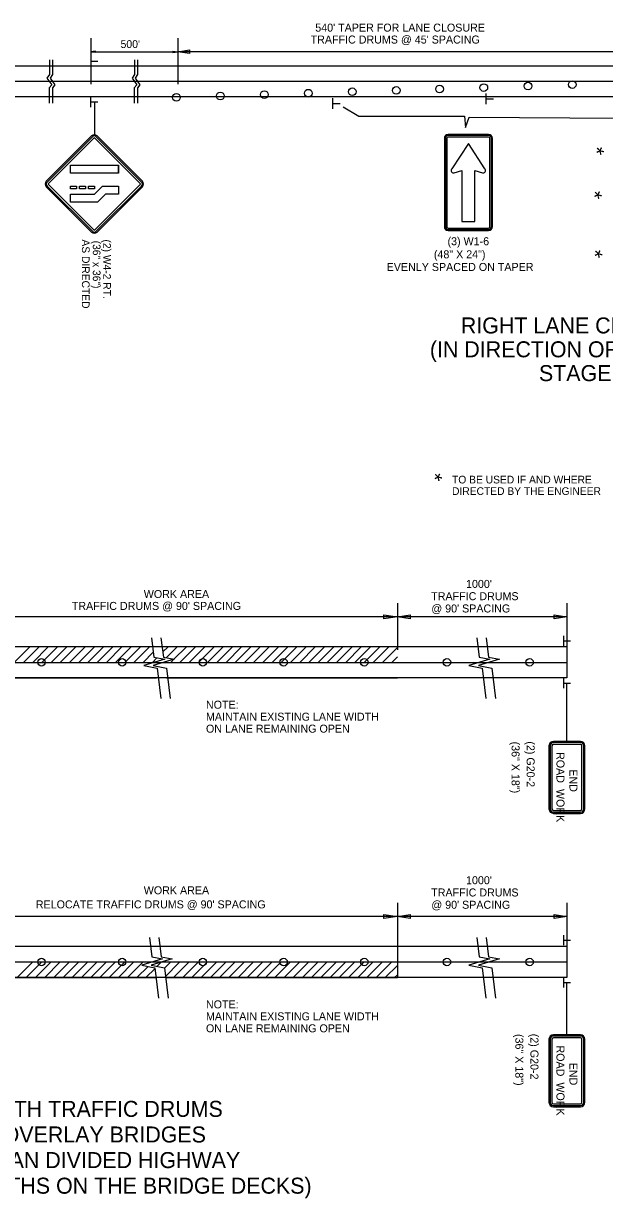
# Model space of a CAD drawing. Extents: x 1930579 to 1938222, y 596452 to 597559.
# Drawn here: x 1937236 to 1937672, y 596558 to 597439 of the extents above; entities that cross this region are included whole.
import ezdxf

# ---------------------------------------------------------------- set-up
doc = ezdxf.new("R2010")
doc.units = 0
for name, color, linetype in [('Default', 7, 'Continuous'), ('P_TC_Signs_Permanent', 7, 'Continuous'), ('P_TC_Signs_Temporary', 7, 'Continuous'), ('R_Border', 7, 'Continuous')]:
    doc.layers.add(name, color=color, linetype=linetype)

msp = doc.modelspace()

# ---------------------------------------------------------------- linework, layer by layer
at = {"layer": 'Default'}
for p, q in [((1937286.15, 597427.55), (1937286.15, 597393.08)), ((1937351.5, 597427.55), (1937351.5, 597393.08)), ((1937289.82, 597417.99), (1937286.15, 597417.44)), ((1937286.15, 597417.44), (1937351.5, 597417.44)), ((1937289.82, 597416.89), (1937286.15, 597417.44)), ((1937286.15, 597414.32), (1937286.15, 597406.66)), ((1937289.82, 597417.9), (1937286.76, 597417.44)), ((1937289.82, 597416.98), (1937286.76, 597417.44)), ((1937289.82, 597417.81), (1937287.4, 597417.44)), ((1937289.82, 597417.08), (1937287.4, 597417.44)), ((1937289.82, 597417.72), (1937288.01, 597417.44)), ((1937289.82, 597417.17), (1937288.01, 597417.44)), ((1937289.82, 597417.62), (1937288.63, 597417.44)), ((1937289.82, 597417.27), (1937288.63, 597417.44)), ((1937289.82, 597417.53), (1937289.24, 597417.44)), ((1937289.82, 597417.36), (1937289.24, 597417.44)), ((1937289.82, 597416.89), (1937289.82, 597417.99)), ((1937347.83, 597417.99), (1937351.5, 597417.44)), ((1937347.83, 597417.99), (1937347.83, 597416.89)), ((1937347.83, 597417.9), (1937350.89, 597417.44)), ((1937347.83, 597417.81), (1937350.25, 597417.44)), ((1937347.83, 597417.72), (1937349.64, 597417.44)), ((1937347.83, 597417.62), (1937349.02, 597417.44)), ((1937347.83, 597417.53), (1937348.41, 597417.44)), ((1937347.83, 597416.89), (1937351.5, 597417.44)), ((1937347.83, 597417.26), (1937349.02, 597417.44)), ((1937347.83, 597417.08), (1937350.25, 597417.44)), ((1937347.83, 597416.98), (1937350.89, 597417.44)), ((1937347.83, 597417.17), (1937349.64, 597417.44)), ((1937347.83, 597417.36), (1937348.41, 597417.44)), ((1937351.5, 597417.44), (1937360.36, 597418.77)), ((1937718.72, 597417.44), (1937351.5, 597417.44)), ((1937360.36, 597416.11), (1937351.5, 597417.44)), ((1937360.36, 597418.77), (1937360.36, 597416.11)), ((1937351.5, 597406.66), (1936683.76, 597406.66)), ((1937286.26, 597410.51), (1937291.49, 597410.51)), ((1937970.45, 597406.66), (1937351.5, 597406.66)), ((1937970.45, 597395.14), (1936683.76, 597395.14)), ((1937582.76, 597378.17), (1937582.76, 597386.15)), ((1937351.5, 597383.62), (1936683.76, 597383.62)), ((1937286.15, 597375.96), (1937286.15, 597383.62)), ((1937286.26, 597379.77), (1937291.49, 597379.77)), ((1937970.45, 597383.62), (1937351.5, 597383.62)), ((1937467.8, 597374.68), (1937467.8, 597382.66)), ((1937467.92, 597378.65), (1937473.37, 597378.65)), ((1937582.88, 597382.14), (1937588.33, 597382.14)), ((1937516.16, 597003.98), (1937516.16, 596968.94)), ((1937643.39, 597003.98), (1937643.39, 596947.87)), ((1937516.16, 596993.7), (1937188.67, 596993.7)), ((1937506.1, 596992.19), (1937506.1, 596995.2)), ((1937506.1, 596995.2), (1937516.16, 596993.7)), ((1937516.16, 596993.7), (1937506.1, 596992.19)), ((1937516.16, 596993.7), (1937525.82, 596995.15)), ((1937525.82, 596992.25), (1937516.16, 596993.7)), ((1937643.39, 596993.7), (1937516.16, 596993.7)), ((1937525.82, 596995.15), (1937525.82, 596992.25)), ((1937633.73, 596992.25), (1937633.73, 596995.15)), ((1937633.73, 596995.15), (1937643.39, 596993.7)), ((1937643.39, 596993.7), (1937633.73, 596992.25)), ((1937640.73, 596979.4), (1937640.73, 596971.92)), ((1937640.84, 596975.68), (1937645.95, 596975.68)), ((1937643.39, 596971.31), (1936696.54, 596971.31)), ((1937228.83, 596959.59), (1937240.55, 596971.31)), ((1937235.73, 596959.59), (1937247.45, 596971.31)), ((1937242.64, 596959.59), (1937254.36, 596971.31)), ((1937249.54, 596959.59), (1937261.26, 596971.31)), ((1937256.45, 596959.59), (1937268.17, 596971.31)), ((1937263.35, 596959.59), (1937275.07, 596971.31)), ((1937270.26, 596959.59), (1937281.98, 596971.31)), ((1937277.16, 596959.59), (1937288.88, 596971.31)), ((1937284.07, 596959.59), (1937295.79, 596971.31)), ((1937290.97, 596959.59), (1937302.69, 596971.31)), ((1937297.88, 596959.59), (1937309.6, 596971.31)), ((1937304.79, 596959.59), (1937316.5, 596971.31)), ((1937311.69, 596959.59), (1937323.41, 596971.31)), ((1937318.6, 596959.59), (1937330.31, 596971.31)), ((1937325.5, 596959.59), (1937333.09, 596967.18)), ((1937332.41, 596959.59), (1937335.81, 596962.99)), ((1937340.18, 596967.37), (1937344.13, 596971.31)), ((1937342.74, 596963.02), (1937351.03, 596971.31)), ((1937348.61, 596961.98), (1937357.94, 596971.31)), ((1937353.12, 596959.59), (1937364.84, 596971.31)), ((1937360.03, 596959.59), (1937371.75, 596971.31)), ((1937366.93, 596959.59), (1937378.65, 596971.31)), ((1937373.84, 596959.59), (1937385.56, 596971.31)), ((1937380.74, 596959.59), (1937392.46, 596971.31)), ((1937387.65, 596959.59), (1937399.37, 596971.31)), ((1937394.55, 596959.59), (1937406.27, 596971.31)), ((1937401.46, 596959.59), (1937413.18, 596971.31)), ((1937408.37, 596959.59), (1937420.08, 596971.31)), ((1937415.27, 596959.59), (1937426.99, 596971.31)), ((1937422.18, 596959.59), (1937433.89, 596971.31)), ((1937429.08, 596959.59), (1937440.8, 596971.31)), ((1937435.99, 596959.59), (1937447.71, 596971.31)), ((1937442.89, 596959.59), (1937454.61, 596971.31)), ((1937449.8, 596959.59), (1937461.52, 596971.31)), ((1937456.7, 596959.59), (1937468.42, 596971.31)), ((1937463.61, 596959.59), (1937475.33, 596971.31)), ((1937470.51, 596959.59), (1937482.23, 596971.31)), ((1937477.42, 596959.59), (1937489.14, 596971.31)), ((1937484.32, 596959.59), (1937496.04, 596971.31)), ((1937491.23, 596959.59), (1937502.95, 596971.31)), ((1937498.13, 596959.59), (1937509.85, 596971.31)), ((1937505.04, 596959.59), (1937516.16, 596970.71)), ((1937511.95, 596959.59), (1937516.16, 596963.8)), ((1936696.54, 596959.59), (1937643.39, 596959.59)), ((1937346.22, 596959.59), (1937348.52, 596961.89)), ((1937643.39, 596947.87), (1936696.54, 596947.87)), ((1937188.46, 596947.87), (1937335.53, 596947.87)), ((1937343, 596947.87), (1937516.16, 596947.87)), ((1937640.73, 596947.64), (1937640.73, 596940.16)), ((1937640.84, 596943.92), (1937645.95, 596943.92)), ((1937516.16, 596779.28), (1937516.16, 596723.17)), ((1937516.16, 596779.28), (1937516.16, 596744.24)), ((1937643.39, 596779.28), (1937643.39, 596723.17)), ((1937516.16, 596769), (1937188.67, 596769)), ((1937506.1, 596767.49), (1937506.1, 596770.5)), ((1937506.1, 596770.5), (1937516.16, 596769)), ((1937516.16, 596769), (1937506.1, 596767.49)), ((1937516.16, 596769), (1937525.82, 596770.45)), ((1937525.82, 596767.55), (1937516.16, 596769)), ((1937643.39, 596769), (1937516.16, 596769)), ((1937525.82, 596770.45), (1937525.82, 596767.55)), ((1937633.73, 596767.55), (1937633.73, 596770.45)), ((1937633.73, 596770.45), (1937643.39, 596769)), ((1937643.39, 596769), (1937633.73, 596767.55)), ((1937640.73, 596754.94), (1937640.73, 596747.46)), ((1937640.84, 596751.22), (1937645.95, 596751.22)), ((1937643.39, 596746.61), (1936696.54, 596746.61)), ((1936696.54, 596734.89), (1937643.39, 596734.89)), ((1937230.92, 596723.17), (1937242.64, 596734.89)), ((1937237.82, 596723.17), (1937249.54, 596734.89)), ((1937244.73, 596723.17), (1937256.45, 596734.89)), ((1937251.63, 596723.17), (1937263.35, 596734.89)), ((1937258.54, 596723.17), (1937270.26, 596734.89)), ((1937265.45, 596723.17), (1937277.16, 596734.89)), ((1937272.35, 596723.17), (1937284.07, 596734.89)), ((1937279.26, 596723.17), (1937290.97, 596734.89)), ((1937286.16, 596723.17), (1937297.88, 596734.89)), ((1937293.07, 596723.17), (1937304.79, 596734.89)), ((1937299.97, 596723.17), (1937311.69, 596734.89)), ((1937306.88, 596723.17), (1937318.6, 596734.89)), ((1937313.78, 596723.17), (1937325.5, 596734.89)), ((1937336.07, 596731.64), (1937339.31, 596734.89)), ((1937341.4, 596723.17), (1937353.12, 596734.89)), ((1937341.5, 596730.17), (1937346.22, 596734.89)), ((1937348.31, 596723.17), (1937360.03, 596734.89)), ((1937355.21, 596723.17), (1937366.93, 596734.89)), ((1937362.12, 596723.17), (1937373.84, 596734.89)), ((1937369.03, 596723.17), (1937380.74, 596734.89)), ((1937375.93, 596723.17), (1937387.65, 596734.89)), ((1937382.84, 596723.17), (1937394.55, 596734.89)), ((1937389.74, 596723.17), (1937401.46, 596734.89)), ((1937396.65, 596723.17), (1937408.37, 596734.89)), ((1937403.55, 596723.17), (1937415.27, 596734.89)), ((1937410.46, 596723.17), (1937422.18, 596734.89)), ((1937417.36, 596723.17), (1937429.08, 596734.89)), ((1937424.27, 596723.17), (1937435.99, 596734.89)), ((1937431.17, 596723.17), (1937442.89, 596734.89)), ((1937438.08, 596723.17), (1937449.8, 596734.89)), ((1937444.98, 596723.17), (1937456.7, 596734.89)), ((1937451.89, 596723.17), (1937463.61, 596734.89)), ((1937458.79, 596723.17), (1937470.51, 596734.89)), ((1937465.7, 596723.17), (1937477.42, 596734.89)), ((1937472.61, 596723.17), (1937484.32, 596734.89)), ((1937479.51, 596723.17), (1937491.23, 596734.89)), ((1937486.42, 596723.17), (1937498.13, 596734.89)), ((1937493.32, 596723.17), (1937505.04, 596734.89)), ((1937500.23, 596723.17), (1937511.95, 596734.89)), ((1937320.69, 596723.17), (1937329.13, 596731.61)), ((1937327.59, 596723.17), (1937334.41, 596729.99)), ((1937507.13, 596723.17), (1937516.16, 596732.19)), ((1937514.04, 596723.17), (1937516.16, 596725.29)), ((1937643.39, 596723.17), (1936696.54, 596723.17)), ((1937188.46, 596723.17), (1937335.53, 596723.17)), ((1937334.5, 596723.17), (1937335.15, 596723.82)), ((1937343, 596723.17), (1937516.16, 596723.17)), ((1937640.73, 596723.18), (1937640.73, 596715.7)), ((1937640.84, 596719.46), (1937645.95, 596719.46))]:
    msp.add_line(p, q, dxfattribs=at)
for points in [[(1937255.22, 597411.46), (1937255.22, 597400.51), (1937253.34, 597397.73), (1937256.99, 597392.74), (1937255.07, 597390.44), (1937255.07, 597378.82)], [(1937257.52, 597411.46), (1937257.52, 597400.41), (1937255.65, 597397.63), (1937259.29, 597392.65), (1937257.37, 597390.34), (1937257.37, 597378.82)], [(1937319.01, 597411.46), (1937319.01, 597400.51), (1937317.14, 597397.73), (1937320.79, 597392.74), (1937318.87, 597390.44), (1937318.87, 597378.82)], [(1937321.31, 597411.46), (1937321.31, 597400.41), (1937319.44, 597397.63), (1937323.09, 597392.65), (1937321.17, 597390.34), (1937321.17, 597378.82)], [(1937331.74, 596978.04), (1937333.57, 596963.38), (1937341.63, 596961.96), (1937325.98, 596957.22), (1937335.94, 596955.32), (1937338.69, 596932.48)], [(1937338.85, 596978.04), (1937340.68, 596963.38), (1937348.74, 596961.96), (1937333.09, 596957.22), (1937343.05, 596955.32), (1937345.8, 596932.48)], [(1937575.66, 596978.04), (1937577.49, 596963.38), (1937585.55, 596961.96), (1937569.9, 596957.22), (1937579.86, 596955.32), (1937582.61, 596932.48)], [(1937582.77, 596978.04), (1937584.6, 596963.38), (1937592.66, 596961.96), (1937577.01, 596957.22), (1937586.97, 596955.32), (1937589.72, 596932.48)], [(1937330.13, 596753.34), (1937331.97, 596738.68), (1937340.03, 596737.26), (1937324.38, 596732.52), (1937334.34, 596730.62), (1937337.08, 596707.78)], [(1937337.25, 596753.34), (1937339.08, 596738.68), (1937347.14, 596737.26), (1937331.49, 596732.52), (1937341.45, 596730.62), (1937344.2, 596707.78)], [(1937575.66, 596753.34), (1937577.49, 596738.68), (1937585.55, 596737.26), (1937569.9, 596732.52), (1937579.86, 596730.62), (1937582.61, 596707.78)], [(1937582.77, 596753.34), (1937584.6, 596738.68), (1937592.66, 596737.26), (1937577.01, 596732.52), (1937586.97, 596730.62), (1937589.72, 596707.78)]]:
    msp.add_lwpolyline(points, dxfattribs=at)
for centre, radius in [((1937614.18, 597391.71), 2.87), ((1937647.33, 597392.81), 2.87), ((1937350.42, 597383.25), 2.87), ((1937383.41, 597384.29), 2.87), ((1937416.39, 597385.33), 2.87), ((1937449.37, 597386.38), 2.87), ((1937482.36, 597387.42), 2.87), ((1937515.34, 597388.47), 2.87), ((1937547.87, 597389.51), 2.87), ((1937581.02, 597390.61), 2.87), ((1937249.21, 596959.59), 2.8), ((1937309.75, 596959.59), 2.8), ((1937370.29, 596959.59), 2.8), ((1937430.82, 596959.59), 2.8), ((1937491.36, 596959.59), 2.8), ((1937553.36, 596959.59), 2.8), ((1937615.36, 596959.59), 2.8), ((1937249.21, 596734.89), 2.8), ((1937309.75, 596734.89), 2.8), ((1937370.29, 596734.89), 2.8), ((1937430.82, 596734.89), 2.8), ((1937491.36, 596734.89), 2.8), ((1937553.36, 596734.89), 2.8), ((1937615.36, 596734.89), 2.8)]:
    msp.add_circle(centre, radius, dxfattribs=at)
at = {"layer": 'P_TC_Signs_Permanent'}
for p, q in [((1937252.82, 597320.38), (1937286.76, 597354.33)), ((1937551.41, 597352.55), (1937551.41, 597286.17)), ((1937552.16, 597352.55), (1937552.16, 597286.17)), ((1937553.29, 597352.55), (1937553.29, 597286.17)), ((1937584.6, 597355.36), (1937554.22, 597355.36)), ((1937584.6, 597354.61), (1937554.22, 597354.61)), ((1937584.6, 597353.49), (1937554.22, 597353.49)), ((1937585.54, 597286.17), (1937585.54, 597352.55)), ((1937586.66, 597286.17), (1937586.66, 597352.55)), ((1937587.41, 597286.17), (1937587.41, 597352.55)), ((1937306.88, 597326.3), (1937306.88, 597332.3)), ((1937286.76, 597282.2), (1937252.82, 597316.14)), ((1937324.94, 597316.14), (1937291, 597282.2)), ((1937554.22, 597285.24), (1937584.6, 597285.24)), ((1937554.22, 597284.11), (1937584.6, 597284.11)), ((1937554.22, 597283.36), (1937584.6, 597283.36))]:
    msp.add_line(p, q, dxfattribs=at)
for points in [[(1937287.39, 597353.69), (1937253.45, 597319.75)], [(1937254.51, 597318.69), (1937288.45, 597352.63)], [(1937289.3, 597352.63), (1937323.24, 597318.69)], [(1937324.3, 597319.75), (1937290.36, 597353.69)], [(1937291, 597354.33), (1937307.97, 597337.36), (1937324.94, 597320.38)], [(1937581.85, 597329.62), (1937569.41, 597348.61), (1937557, 597329.61)], [(1937558.78, 597326.66), (1937564.54, 597328.38), (1937564.54, 597290.11), (1937574.29, 597290.11), (1937574.29, 597328.38), (1937580.03, 597326.63)], [(1937253.45, 597316.78), (1937287.39, 597282.84)], [(1937288.45, 597283.9), (1937254.51, 597317.84)], [(1937323.24, 597317.84), (1937289.3, 597283.9)], [(1937290.36, 597282.84), (1937324.3, 597316.78)]]:
    msp.add_lwpolyline(points, dxfattribs=at)
for points in [[(1937270.88, 597326.3), (1937270.88, 597332.3), (1937306.88, 597332.3), (1937306.88, 597326.3)], [(1937270.88, 597314.66), (1937270.88, 597316.76), (1937275.38, 597316.76), (1937275.38, 597314.66)], [(1937270.88, 597304.76), (1937270.88, 597310.76), (1937288.88, 597310.76), (1937294.88, 597316.76), (1937306.88, 597316.76), (1937306.88, 597310.76), (1937297.36, 597310.76), (1937291.36, 597304.76)], [(1937277.63, 597314.66), (1937277.63, 597316.76), (1937282.13, 597316.76), (1937282.13, 597314.66)], [(1937284.38, 597314.66), (1937284.38, 597316.76), (1937288.88, 597316.76), (1937288.88, 597314.66)]]:
    msp.add_lwpolyline(points, close=True, dxfattribs=at)
for centre, radius, start, end in [((1937288.88, 597352.2), 3, 45, 135), ((1937288.88, 597352.2), 2.1, 45, 135), ((1937288.88, 597352.2), 0.6, 45, 135), ((1937554.22, 597352.55), 2.81, 90, 180), ((1937554.22, 597352.55), 2.06, 90, 180), ((1937554.22, 597352.55), 0.938, 90, 180), ((1937584.6, 597352.55), 2.81, 360, 90), ((1937584.6, 597352.55), 2.06, 360, 90), ((1937584.6, 597352.55), 0.938, 360, 90), ((1937558.29, 597328.36), 1.76, 146.59943, 285.96908), ((1937494.2, 597370.61), 75, 326.59943, 326.85697), ((1937580.53, 597328.36), 1.8, 254.03093, 33.47548), ((1937644.59, 597370.72), 75, 213.2286, 213.47548), ((1937254.94, 597318.26), 3, 135, 225), ((1937254.94, 597318.26), 2.1, 135, 225), ((1937254.94, 597318.26), 0.6, 135, 225), ((1937322.82, 597318.26), 0.6, 315, 45), ((1937322.82, 597318.26), 2.1, 315, 45), ((1937322.82, 597318.26), 3, 315, 45), ((1937288.88, 597284.32), 3, 225, 315), ((1937288.88, 597284.32), 2.1, 225, 315), ((1937288.88, 597284.32), 0.6, 225, 315), ((1937554.22, 597286.17), 2.81, 180, 270), ((1937554.22, 597286.17), 2.06, 180, 270), ((1937554.22, 597286.17), 0.937, 180, 270), ((1937584.6, 597286.17), 2.81, 270, 360), ((1937584.6, 597286.17), 2.06, 270, 360), ((1937584.6, 597286.17), 0.938, 270, 360)]:
    msp.add_arc(centre, radius, start, end, dxfattribs=at)
at = {"layer": 'P_TC_Signs_Temporary'}
for p, q in [((1937629.89, 596896.98), (1937629.89, 596849.73)), ((1937630.83, 596896.98), (1937630.83, 596849.73)), ((1937632.14, 596896.98), (1937632.14, 596849.73)), ((1937653.52, 596900.35), (1937633.27, 596900.35)), ((1937653.52, 596899.42), (1937633.27, 596899.42)), ((1937653.52, 596898.1), (1937633.27, 596898.1)), ((1937654.64, 596849.73), (1937654.64, 596896.98)), ((1937655.96, 596849.73), (1937655.96, 596896.98)), ((1937656.89, 596849.73), (1937656.89, 596896.98)), ((1937633.27, 596848.6), (1937653.52, 596848.6)), ((1937633.27, 596847.29), (1937653.52, 596847.29)), ((1937633.27, 596846.35), (1937653.52, 596846.35)), ((1937629.89, 596676.95), (1937629.89, 596629.7)), ((1937630.83, 596676.95), (1937630.83, 596629.7)), ((1937632.14, 596676.95), (1937632.14, 596629.7)), ((1937653.52, 596680.33), (1937633.27, 596680.33)), ((1937653.52, 596679.39), (1937633.27, 596679.39)), ((1937653.52, 596678.08), (1937633.27, 596678.08)), ((1937654.64, 596629.7), (1937654.64, 596676.95)), ((1937655.96, 596629.7), (1937655.96, 596676.95)), ((1937656.89, 596629.7), (1937656.89, 596676.95)), ((1937633.27, 596628.58), (1937653.52, 596628.58)), ((1937633.27, 596627.26), (1937653.52, 596627.26)), ((1937633.27, 596626.33), (1937653.52, 596626.33))]:
    msp.add_line(p, q, dxfattribs=at)
for centre, radius, start, end in [((1937633.27, 596896.98), 3.37, 90, 180), ((1937633.27, 596896.98), 2.44, 90, 180), ((1937633.27, 596896.98), 1.13, 90, 180), ((1937653.52, 596896.98), 3.37, 360, 90), ((1937653.52, 596896.98), 2.44, 360, 90), ((1937653.52, 596896.98), 1.13, 360, 90), ((1937633.27, 596849.73), 3.37, 180, 270), ((1937633.27, 596849.73), 2.44, 180, 270), ((1937633.27, 596849.73), 1.13, 180, 270), ((1937653.52, 596849.73), 2.44, 270, 360), ((1937653.52, 596849.73), 1.13, 270, 360), ((1937653.52, 596849.73), 3.38, 270, 360), ((1937633.27, 596676.95), 3.37, 90, 180), ((1937633.27, 596676.95), 2.44, 90, 180), ((1937633.27, 596676.95), 1.13, 90, 180), ((1937653.52, 596676.95), 3.37, 360, 90), ((1937653.52, 596676.95), 2.44, 360, 90), ((1937653.52, 596676.95), 1.13, 360, 90), ((1937633.27, 596629.7), 3.37, 180, 270), ((1937633.27, 596629.7), 2.44, 180, 270), ((1937633.27, 596629.7), 1.13, 180, 270), ((1937653.52, 596629.7), 2.44, 270, 360), ((1937653.52, 596629.7), 1.13, 270, 360), ((1937653.52, 596629.7), 3.38, 270, 360)]:
    msp.add_arc(centre, radius, start, end, dxfattribs=at)
at = {"layer": 'R_Border'}
for p, q in [((1937288.88, 597379.77), (1937288.88, 597355.2)), ((1937643.39, 596900.35), (1937643.39, 596943.92)), ((1937643.39, 596680.33), (1937643.39, 596719.46))]:
    msp.add_line(p, q, dxfattribs=at)
msp.add_lwpolyline([(1937475.48, 597376.04), (1937487.29, 597369.09), (1937566.49, 597369.09), (1937567.19, 597360.75), (1937569.97, 597368.39), (1937683.22, 597367.7), (1937696.42, 597379.52)], dxfattribs=at)

# ---------------------------------------------------------------- texts
at = {"layer": 'Default'}
for s, height, p in [("540' TAPER FOR LANE CLOSURE", 6, (1937454.6, 597432.54)), ("TRAFFIC DRUMS @ 45' SPACING ", 6, (1937451.11, 597423.59)), ("500'", 5.875, (1937308.51, 597420.24)), ('RIGHT LANE CLOSURE ', 12, (1937563.79, 597206.21)), ('(IN DIRECTION OF TRAFFIC)', 12, (1937540.55, 597188.33)), ('STAGE 2', 12, (1937622.37, 597170.46)), ("1000'", 6, (1937567.68, 597015.4)), ('WORK AREA', 6, (1937325.96, 597007.82)), ('TRAFFIC DRUMS ', 6, (1937541.56, 597006.2)), ("TRAFFIC DRUMS @ 90' SPACING", 6, (1937271.98, 596998.9)), ("@ 90' SPACING", 6, (1937541.66, 596996.99)), ("1000'", 6, (1937567.68, 596793.22)), ('WORK AREA', 6, (1937325.95, 596785.65)), ('TRAFFIC DRUMS ', 6, (1937541.56, 596784.03)), ("RELOCATE TRAFFIC DRUMS @ 90' SPACING", 6, (1937244.98, 596775.09)), ("@ 90' SPACING", 6, (1937541.66, 596774.81)), ('LANE CLOSURE WITH TRAFFIC DRUMS', 12, (1937080.32, 596618.76)), ('FOR POLYMER OVERLAY BRIDGES', 12, (1937098.84, 596599.56)), ('4 LANE GRASS MEDIAN DIVIDED HIGHWAY', 12, (1937064.83, 596580.36)), ('(VAR. CLEAR ROADWAY WIDTHS ON THE BRIDGE DECKS)', 12, (1936999.82, 596561.16))]:
    msp.add_text(s, height=height, rotation=360, dxfattribs=at).set_placement(p)
at = {"layer": 'P_TC_Signs_Temporary'}
for s, p in [('ROAD  WORK', (1937635.52, 596892.31)), ('END', (1937645.27, 596879.38)), ('ROAD  WORK', (1937635.52, 596672.29)), ('END', (1937645.27, 596659.36))]:
    msp.add_text(s, height=6, rotation=270, dxfattribs=at).set_placement(p)
at = {"layer": 'R_Border'}
for s, height, rotation, p in [('*', 11.52, 45, (1937672.03, 597335.03)), ('*', 11.52, 45, (1937670.45, 597301.99)), ('AS DIRECTED ', 5.76, 270, (1937279.57, 597276.69)), ('(36" x 36")', 5.76, 270, (1937287.73, 597275.81)), ('(2) W4-2 RT.', 5.76, 270, (1937295.53, 597276.69)), ('(3) W1-6', 6, 0.00754, (1937553.8, 597272.36)), ('(48" X 24")', 6, 0.00754, (1937543.57, 597262.56)), ('*', 11.52, 45, (1937670.84, 597257.77)), ('EVENLY SPACED ON TAPER', 6, 0.00754, (1937508.16, 597253.06)), ('*', 11.52, 45, (1937550.61, 597090.36)), ('TO BE USED IF AND WHERE ', 5.76, 360, (1937557.18, 597093.75)), ('DIRECTED BY THE ENGINEER', 5.76, 360, (1937557.18, 597085.11)), ('NOTE:', 6, 360, (1937372.6, 596924.82)), ('MAINTAIN EXISTING LANE WIDTH', 6, 360, (1937372.6, 596915.84)), ('ON LANE REMAINING OPEN', 6, 360, (1937372.6, 596906.86)), ('(36" X 18")', 6, 270, (1937601.85, 596900.15)), ('(2) G20-2', 6, 270, (1937613.15, 596900.35)), ('NOTE:', 6, 360, (1937372.6, 596700.12)), ('MAINTAIN EXISTING LANE WIDTH', 6, 360, (1937372.6, 596691.14)), ('ON LANE REMAINING OPEN', 6, 360, (1937372.6, 596682.16)), ('(36" X 18")', 6, 270, (1937604.68, 596680.9)), ('(2) G20-2', 6, 270, (1937615.99, 596681.1))]:
    msp.add_text(s, height=height, rotation=rotation, dxfattribs=at).set_placement(p)

doc.saveas('drawing.dxf')
